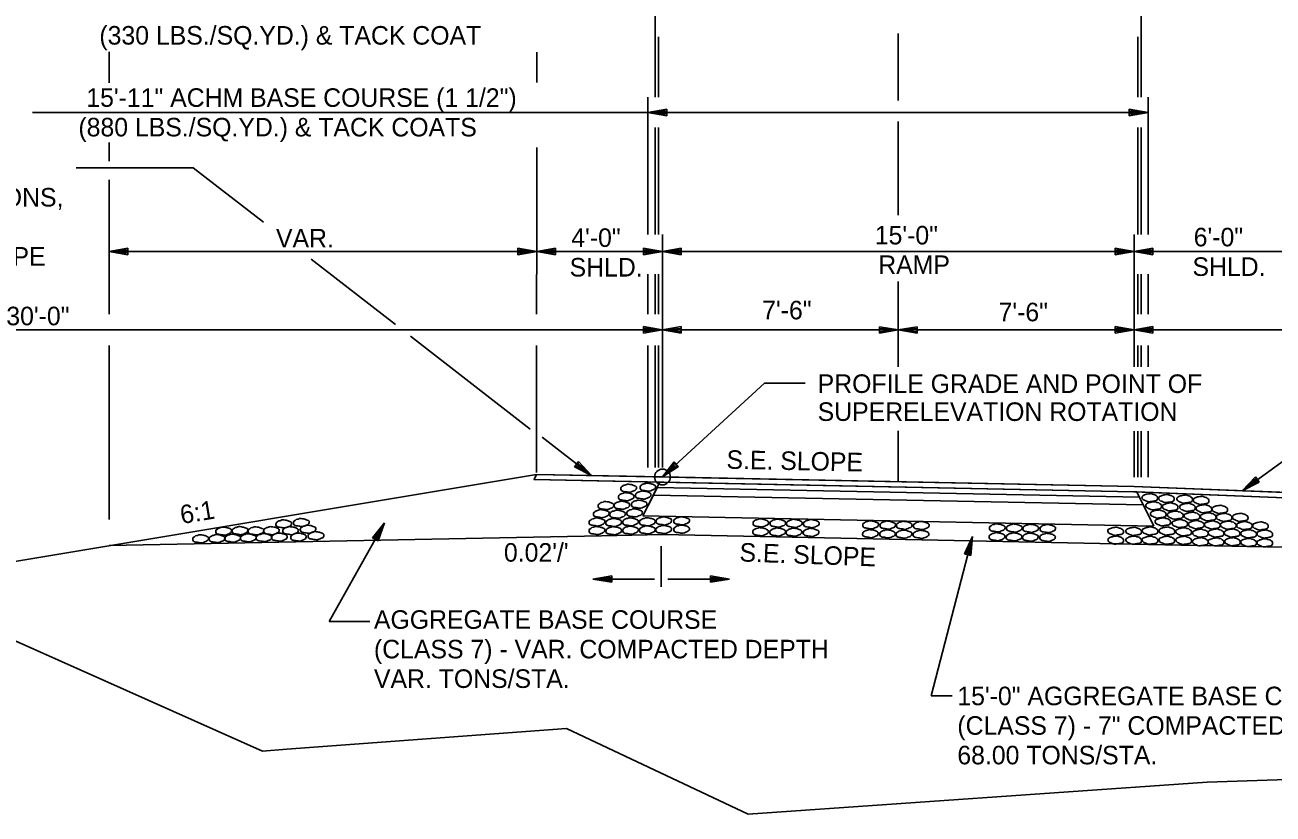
# Model space of a CAD drawing. Extents: x 1734743 to 1735935, y 759845 to 763831.
# Drawn here: x 1735729.77 to 1735769.47, y 762681.39 to 762706.48 of the extents above; entities that cross this region are included whole.
import ezdxf

# ---------------------------------------------------------------- set-up
doc = ezdxf.new("R2010")
doc.units = 0
for name, color, linetype in [('1', 7, 'Continuous'), ('19', 7, 'Continuous'), ('8', 7, 'Continuous'), ('Level 1', 7, 'Continuous'), ('Level 9', 7, 'Continuous'), ('R_Prop Surface', 7, 'Continuous')]:
    doc.layers.add(name, color=color, linetype=linetype)

# ---------------------------------------------------------------- blocks, each defined once
blk = doc.blocks.new('TM')
at = {"layer": '8'}
for p, q in [((-120.309, 21.181), (-119.787, -20.829)), ((0, 0), (-120.309, 21.181)), ((-31.382, 2.945), (-120.176, 10.512)), ((-119.787, -20.829), (0, 0)), ((-119.911, -10.826), (-31.307, -3.057))]:
    blk.add_line(p, q, dxfattribs=at)
blk = doc.blocks.new('ROCKS')
at = {"layer": '1'}
blk.add_spline([(0.013, 0.06), (0.053, 0.053), (0.107, 0.033), (0.133, 0.013), (0.133, -0.007), (0.12, -0.033), (0.107, -0.04), (0.073, -0.053), (0.033, -0.067), (0.013, -0.067), (-0.02, -0.06), (-0.06, -0.053), (-0.087, -0.047), (-0.113, -0.02), (-0.113, -0.007), (-0.107, 0.02), (-0.087, 0.033), (-0.067, 0.047), (-0.033, 0.053), (-0.02, 0.06), (0.013, 0.06)], degree=3, dxfattribs=at)

msp = doc.modelspace()

# ---------------------------------------------------------------- linework, layer by layer
at = {"layer": '19'}
for p, q in [((1735749.814, 762704.185), (1735749.814, 762707.074)), ((1735765.269, 762704.185), (1735765.269, 762707.074)), ((1735749.92, 762704.185), (1735749.92, 762706.104)), ((1735757.548, 762704.077), (1735757.548, 762706.215)), ((1735765.165, 762704.185), (1735765.165, 762706.104)), ((1735732.446, 762704.64), (1735732.446, 762705.631)), ((1735746.047, 762704.651), (1735746.047, 762705.614)), ((1735749.582, 762699.821), (1735749.582, 762704.185)), ((1735765.495, 762699.821), (1735765.495, 762704.185)), ((1735730.014, 762703.7), (1735749.582, 762703.7)), ((1735750.182, 762703.805), (1735749.582, 762703.7)), ((1735749.582, 762699.821), (1735749.582, 762703.7)), ((1735749.582, 762703.7), (1735765.495, 762703.7)), ((1735749.582, 762703.7), (1735750.182, 762703.595)), ((1735750.182, 762703.75), (1735749.742, 762703.715)), ((1735749.742, 762703.685), (1735750.182, 762703.645)), ((1735750.182, 762703.595), (1735750.182, 762703.805)), ((1735764.895, 762703.805), (1735764.895, 762703.595)), ((1735765.495, 762703.7), (1735764.895, 762703.805)), ((1735765.335, 762703.715), (1735764.895, 762703.75)), ((1735764.895, 762703.595), (1735765.495, 762703.7)), ((1735764.895, 762703.645), (1735765.335, 762703.685)), ((1735749.814, 762699.821), (1735749.814, 762703.215)), ((1735749.92, 762699.821), (1735749.92, 762703.215)), ((1735757.547, 762700.429), (1735757.548, 762703.406)), ((1735765.165, 762699.821), (1735765.165, 762703.215)), ((1735765.269, 762699.821), (1735765.269, 762703.215)), ((1735732.446, 762702.153), (1735732.446, 762702.744)), ((1735746.047, 762699.821), (1735746.047, 762702.582)), ((1735731.401, 762701.942), (1735735.119, 762701.942)), ((1735735.119, 762701.942), (1735737.356, 762700.207)), ((1735732.446, 762697.285), (1735732.446, 762701.554)), ((1735746.046, 762697.285), (1735746.047, 762699.821)), ((1735746.046, 762697.285), (1735746.047, 762699.821)), ((1735750.046, 762692.405), (1735750.047, 762699.821)), ((1735750.046, 762692.405), (1735750.047, 762699.821)), ((1735765.046, 762695.613), (1735765.047, 762699.819)), ((1735733.046, 762699.381), (1735732.446, 762699.276)), ((1735732.446, 762699.276), (1735746.046, 762699.275)), ((1735732.446, 762699.276), (1735733.046, 762699.171)), ((1735733.046, 762699.326), (1735732.606, 762699.291)), ((1735732.606, 762699.261), (1735733.046, 762699.221)), ((1735733.046, 762699.171), (1735733.046, 762699.381)), ((1735745.447, 762699.38), (1735745.447, 762699.17)), ((1735746.047, 762699.275), (1735745.447, 762699.38)), ((1735745.887, 762699.29), (1735745.447, 762699.325)), ((1735745.447, 762699.17), (1735746.047, 762699.275)), ((1735745.447, 762699.22), (1735745.887, 762699.26)), ((1735746.647, 762699.381), (1735746.047, 762699.276)), ((1735746.047, 762699.276), (1735750.047, 762699.275)), ((1735746.047, 762699.276), (1735746.647, 762699.171)), ((1735746.647, 762699.326), (1735746.207, 762699.291)), ((1735746.207, 762699.261), (1735746.647, 762699.221)), ((1735746.647, 762699.171), (1735746.647, 762699.381)), ((1735749.447, 762699.381), (1735749.447, 762699.171)), ((1735750.047, 762699.275), (1735749.447, 762699.381)), ((1735749.887, 762699.29), (1735749.447, 762699.326)), ((1735749.447, 762699.171), (1735750.047, 762699.275)), ((1735749.447, 762699.221), (1735749.887, 762699.26)), ((1735750.647, 762699.381), (1735750.047, 762699.276)), ((1735750.047, 762699.276), (1735750.647, 762699.171)), ((1735750.047, 762699.275), (1735765.047, 762699.275)), ((1735750.647, 762699.326), (1735750.207, 762699.291)), ((1735750.207, 762699.261), (1735750.647, 762699.221)), ((1735750.647, 762699.171), (1735750.647, 762699.381)), ((1735764.447, 762699.381), (1735764.447, 762699.171)), ((1735765.047, 762699.275), (1735764.447, 762699.381)), ((1735764.887, 762699.29), (1735764.447, 762699.326)), ((1735764.447, 762699.171), (1735765.047, 762699.275)), ((1735764.447, 762699.221), (1735764.887, 762699.26)), ((1735765.647, 762699.38), (1735765.047, 762699.275)), ((1735765.047, 762699.275), (1735771.047, 762699.275)), ((1735765.047, 762699.275), (1735765.647, 762699.17)), ((1735765.647, 762699.325), (1735765.207, 762699.29)), ((1735765.207, 762699.26), (1735765.647, 762699.22)), ((1735765.647, 762699.17), (1735765.647, 762699.38)), ((1735738.871, 762699.032), (1735741.551, 762696.953)), ((1735749.582, 762697.285), (1735749.582, 762698.553)), ((1735749.813, 762697.285), (1735749.813, 762698.553)), ((1735749.92, 762697.285), (1735749.92, 762698.553)), ((1735757.546, 762695.613), (1735757.547, 762698.325)), ((1735765.165, 762697.284), (1735765.165, 762698.553)), ((1735765.269, 762697.284), (1735765.269, 762698.553)), ((1735765.495, 762697.284), (1735765.495, 762698.553)), ((1735720.041, 762696.787), (1735750.046, 762696.784)), ((1735749.441, 762696.888), (1735749.441, 762696.678)), ((1735750.041, 762696.783), (1735749.441, 762696.888)), ((1735749.881, 762696.798), (1735749.441, 762696.833)), ((1735749.441, 762696.678), (1735750.041, 762696.783)), ((1735749.441, 762696.728), (1735749.881, 762696.768)), ((1735750.046, 762696.785), (1735757.546, 762696.785)), ((1735750.647, 762696.886), (1735750.047, 762696.781)), ((1735750.047, 762696.781), (1735750.647, 762696.676)), ((1735750.647, 762696.831), (1735750.207, 762696.796)), ((1735750.207, 762696.766), (1735750.647, 762696.726)), ((1735750.647, 762696.676), (1735750.647, 762696.886)), ((1735756.947, 762696.885), (1735756.947, 762696.675)), ((1735757.547, 762696.78), (1735756.947, 762696.885)), ((1735757.387, 762696.795), (1735756.947, 762696.83)), ((1735756.947, 762696.675), (1735757.547, 762696.78)), ((1735756.947, 762696.725), (1735757.387, 762696.765)), ((1735757.546, 762696.785), (1735765.046, 762696.784)), ((1735758.147, 762696.885), (1735757.547, 762696.78)), ((1735757.547, 762696.78), (1735758.147, 762696.675)), ((1735758.147, 762696.83), (1735757.707, 762696.795)), ((1735757.707, 762696.765), (1735758.147, 762696.725)), ((1735758.147, 762696.675), (1735758.147, 762696.885)), ((1735764.446, 762696.889), (1735764.446, 762696.679)), ((1735765.046, 762696.784), (1735764.446, 762696.889)), ((1735764.886, 762696.799), (1735764.446, 762696.834)), ((1735764.446, 762696.679), (1735765.046, 762696.784)), ((1735764.446, 762696.729), (1735764.886, 762696.769)), ((1735765.646, 762696.889), (1735765.046, 762696.784)), ((1735765.046, 762696.784), (1735765.646, 762696.679)), ((1735765.046, 762696.784), (1735795.041, 762696.782)), ((1735765.646, 762696.834), (1735765.206, 762696.799)), ((1735765.206, 762696.769), (1735765.646, 762696.729)), ((1735765.646, 762696.679), (1735765.646, 762696.889)), ((1735742.03, 762696.581), (1735745.838, 762693.627)), ((1735732.446, 762690.751), (1735732.446, 762696.285)), ((1735746.046, 762692.246), (1735746.046, 762696.285)), ((1735746.046, 762692.246), (1735746.046, 762696.285)), ((1735749.581, 762692.405), (1735749.581, 762696.285)), ((1735749.813, 762692.405), (1735749.813, 762696.285)), ((1735749.919, 762692.405), (1735749.919, 762696.285)), ((1735765.165, 762695.613), (1735765.165, 762696.284)), ((1735765.269, 762695.613), (1735765.269, 762696.284)), ((1735765.495, 762695.613), (1735765.495, 762696.284)), ((1735753.294, 762695.086), (1735750.046, 762692.105)), ((1735754.584, 762695.086), (1735753.294, 762695.086)), ((1735757.546, 762691.955), (1735757.547, 762693.568)), ((1735765.046, 762692.104), (1735765.046, 762693.567)), ((1735765.165, 762692.104), (1735765.165, 762693.567)), ((1735765.269, 762692.104), (1735765.269, 762693.567)), ((1735765.495, 762692.104), (1735765.495, 762693.567)), ((1735746.216, 762693.37), (1735747.788, 762692.151)), ((1735768.483, 762691.667), (1735770.684, 762693.264)), ((1735747.245, 762692.428), (1735747.372, 762692.595)), ((1735747.788, 762692.151), (1735747.245, 762692.428)), ((1735747.655, 762692.238), (1735747.282, 762692.468)), ((1735747.346, 762692.556), (1735747.668, 762692.26)), ((1735747.372, 762692.595), (1735747.788, 762692.151)), ((1735750.046, 762692.105), (1735750.418, 762692.588)), ((1735750.558, 762692.434), (1735750.046, 762692.105)), ((1735750.156, 762692.22), (1735750.45, 762692.545)), ((1735750.525, 762692.465), (1735750.175, 762692.203)), ((1735750.418, 762692.588), (1735750.558, 762692.434)), ((1735746.046, 762692.186), (1735720.048, 762687.858)), ((1735745.963, 762692.021), (1735765.043, 762691.638)), ((1735746.046, 762692.186), (1735765.046, 762691.804)), ((1735768.483, 762691.667), (1735768.905, 762692.105)), ((1735768.604, 762691.769), (1735768.933, 762692.059)), ((1735768.998, 762691.972), (1735768.621, 762691.75)), ((1735768.905, 762692.105), (1735769.028, 762691.937)), ((1735749.881, 762691.775), (1735749.757, 762691.528)), ((1735749.881, 762691.775), (1735765.214, 762691.467)), ((1735765.214, 762691.467), (1735749.881, 762691.775)), ((1735765.039, 762691.638), (1735771.131, 762691.394)), ((1735765.046, 762691.804), (1735771.046, 762691.564)), ((1735769.028, 762691.937), (1735768.483, 762691.667)), ((1735749.757, 762691.528), (1735749.427, 762690.868)), ((1735749.757, 762691.528), (1735765.341, 762691.215)), ((1735749.757, 762691.528), (1735765.341, 762691.215)), ((1735765.341, 762691.215), (1735749.757, 762691.528)), ((1735765.341, 762691.215), (1735765.214, 762691.467)), ((1735765.677, 762690.541), (1735765.341, 762691.215)), ((1735749.427, 762690.868), (1735765.677, 762690.541)), ((1735749.427, 762690.868), (1735765.677, 762690.541)), ((1735739.449, 762687.514), (1735741.205, 762690.647)), ((1735740.821, 762690.175), (1735741.205, 762690.647)), ((1735740.862, 762690.155), (1735741.113, 762690.514)), ((1735741.136, 762690.503), (1735740.958, 762690.103)), ((1735741.205, 762690.647), (1735741.002, 762690.072)), ((1735748.108, 762690.233), (1735732.446, 762689.922)), ((1735741.002, 762690.072), (1735740.821, 762690.175)), ((1735750.046, 762690.272), (1735748.108, 762690.233)), ((1735750.046, 762690.272), (1735767.056, 762689.93)), ((1735758.588, 762685.141), (1735759.905, 762690.214)), ((1735759.653, 762689.66), (1735759.905, 762690.214)), ((1735759.699, 762689.651), (1735759.85, 762690.062)), ((1735759.875, 762690.058), (1735759.805, 762689.625)), ((1735759.905, 762690.214), (1735759.855, 762689.607)), ((1735750.006, 762689.903), (1735750.006, 762688.615)), ((1735759.855, 762689.607), (1735759.653, 762689.66)), ((1735767.055, 762689.93), (1735782.73, 762689.615)), ((1735749.789, 762688.853), (1735747.835, 762688.853)), ((1735750.222, 762688.853), (1735752.177, 762688.853)), ((1735740.739, 762687.514), (1735739.449, 762687.514)), ((1735759.264, 762685.141), (1735758.588, 762685.141))]:
    msp.add_line(p, q, dxfattribs=at)
for points in [[(1735680.306, 762694.946), (1735680.306, 762694.946), (1735680.306, 762694.946), (1735688.042, 762694.993), (1735690.336, 762695.104), (1735696.399, 762695.063), (1735703.199, 762694.723), (1735715.078, 762692.342), (1735728.668, 762687.241), (1735737.329, 762683.386), (1735738.102, 762683.447)], [(1735771.131, 762691.394), (1735765.131, 762691.634), (1735765.041, 762691.638), (1735749.964, 762691.94), (1735749.964, 762691.94), (1735749.964, 762691.94), (1735745.963, 762692.021), (1735746.046, 762692.186), (1735746.046, 762692.186), (1735750.046, 762692.105), (1735765.046, 762691.804), (1735771.046, 762691.564), (1735771.046, 762691.564), (1735771.131, 762691.394), (1735771.131, 762691.394), (1735771.131, 762691.394)], [(1735765.214, 762691.467), (1735749.881, 762691.775), (1735749.881, 762691.775), (1735749.964, 762691.94), (1735749.964, 762691.94), (1735765.041, 762691.638), (1735765.131, 762691.634), (1735765.131, 762691.634), (1735765.131, 762691.634), (1735765.131, 762691.634), (1735765.214, 762691.467), (1735765.214, 762691.467), (1735765.214, 762691.467)], [(1735738.102, 762683.447), (1735746.995, 762684.106), (1735752.775, 762681.385), (1735767.375, 762682.404), (1735787.755, 762683.082), (1735799.985, 762684.441), (1735809.495, 762682.741), (1735820.81, 762685.178), (1735822.413, 762684.867)]]:
    msp.add_lwpolyline(points, dxfattribs=at)
at = {"layer": 'Level 9'}
msp.add_circle((1735750.046, 762692.105), 0.25, dxfattribs=at)
at = {"layer": 'R_Prop Surface'}
for p, q in [((1735746.046, 762692.186), (1735745.963, 762692.021)), ((1735749.964, 762691.94), (1735749.427, 762690.868)), ((1735765.131, 762691.634), (1735765.677, 762690.541))]:
    msp.add_line(p, q, dxfattribs=at)

# ---------------------------------------------------------------- block references
at = {"layer": '19', "xscale": 0.0050063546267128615}
for p, yscale, rotation in [((1735747.833, 762688.851), -0.00500635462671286, -179.20057588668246), ((1735752.178, 762688.851), 0.00500635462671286, -0.7994241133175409)]:
    msp.add_blockref('TM', p, dxfattribs=dict(at, yscale=yscale, rotation=rotation))
at = {"layer": 'Level 1'}
for p, xscale, yscale, rotation in [((1735748.873, 762691.483), 2.011654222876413, 2.0116542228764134, 2.041282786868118), ((1735748.95, 762691.751), 2.011654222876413, 2.0116542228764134, 2.041282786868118), ((1735749.414, 762691.537), 2.011654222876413, 2.0116542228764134, 2.041282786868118), ((1735749.561, 762691.786), 2.011654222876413, 2.0116542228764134, 2.041282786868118), ((1735765.567, 762691.452), 2.0116542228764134, -2.011654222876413, 177.9586193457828), ((1735748.228, 762691.201), 2.011654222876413, 2.0116542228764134, 2.041282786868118), ((1735748.734, 762691.21), 2.011654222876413, 2.0116542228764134, 2.041282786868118), ((1735749.285, 762691.245), 2.011654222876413, 2.0116542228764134, 2.041282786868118), ((1735765.691, 762691.193), 2.0116542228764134, -2.011654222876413, 177.9586193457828), ((1735766.099, 762691.423), 2.0116542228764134, -2.011654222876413, 177.9586193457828), ((1735766.217, 762691.158), 2.0116542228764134, -2.011654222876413, 177.9586193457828), ((1735766.679, 762691.407), 2.011654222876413, -2.0116542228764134, 177.95871721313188), ((1735766.766, 762691.145), 2.011654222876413, -2.0116542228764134, 177.95871721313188), ((1735767.198, 762691.367), 2.011654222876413, -2.0116542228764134, 177.95871721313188), ((1735767.289, 762691.1), 2.011654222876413, -2.0116542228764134, 177.95871721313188), ((1735767.793, 762691.08), 2.011654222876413, -2.0116542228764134, 177.95871721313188), ((1735738.539, 762690.662), 2.011654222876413, 2.011654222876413, 1.8263814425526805), ((1735747.943, 762690.679), 2.011654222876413, 2.0116542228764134, 2.041282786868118), ((1735748.082, 762690.944), 2.011654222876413, 2.0116542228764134, 2.041282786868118), ((1735748.476, 762690.663), 2.011654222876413, 2.0116542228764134, 2.041282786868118), ((1735748.597, 762690.926), 2.011654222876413, 2.0116542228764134, 2.041282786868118), ((1735749.01, 762690.683), 2.011654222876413, 2.0116542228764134, 2.041282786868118), ((1735749.138, 762690.968), 2.011654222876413, 2.0116542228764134, 2.041282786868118), ((1735749.545, 762690.685), 2.011654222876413, 2.0116542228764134, 2.041282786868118), ((1735750.069, 762690.711), 2.011654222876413, 2.0116542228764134, 2.041282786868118), ((1735750.639, 762690.715), 2.011654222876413, 2.0116542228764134, 2.041282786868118), ((1735753.154, 762690.649), 2.011654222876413, 2.011654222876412, 1.0597939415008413), ((1735753.697, 762690.641), 2.011654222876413, 2.011654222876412, 1.0597939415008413), ((1735765.836, 762690.932), 2.0116542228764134, -2.011654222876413, 177.9586193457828), ((1735765.983, 762690.683), 2.0116542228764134, -2.011654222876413, 177.9586193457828), ((1735766.381, 762690.897), 2.0116542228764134, -2.011654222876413, 177.9586193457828), ((1735766.91, 762690.863), 2.0116542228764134, -2.011654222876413, 177.9586193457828), ((1735767.427, 762690.843), 2.011654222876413, -2.0116542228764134, 177.95871721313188), ((1735767.932, 762690.827), 2.011654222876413, -2.0116542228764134, 177.95871721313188), ((1735768.444, 762690.825), 2.011654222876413, -2.0116542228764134, 177.95871721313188), ((1735736.07, 762690.389), 2.011654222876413, 2.011654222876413, 1.8263814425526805), ((1735736.591, 762690.404), 2.011654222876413, 2.011654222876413, 1.8263814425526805), ((1735737.097, 762690.397), 2.011654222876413, 2.011654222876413, 1.8263814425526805), ((1735737.59, 762690.403), 2.011654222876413, 2.011654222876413, 1.8263814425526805), ((1735737.981, 762690.618), 2.011654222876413, 2.011654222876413, 1.8263814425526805), ((1735738.198, 762690.403), 2.011654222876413, 2.011654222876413, 1.8263814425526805), ((1735738.756, 762690.447), 2.011654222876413, 2.011654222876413, 1.8263814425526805), ((1735739.008, 762690.242), 2.011654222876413, 2.011654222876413, 1.8263814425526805), ((1735747.944, 762690.408), 2.011654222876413, 2.0116542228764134, 2.041282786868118), ((1735748.477, 762690.402), 2.011654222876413, 2.0116542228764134, 2.041282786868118), ((1735749.011, 762690.418), 2.011654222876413, 2.0116542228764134, 2.041282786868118), ((1735749.546, 762690.429), 2.011654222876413, 2.0116542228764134, 2.041282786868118), ((1735750.065, 762690.441), 2.011654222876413, 2.0116542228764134, 2.041282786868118), ((1735750.635, 762690.451), 2.011654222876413, 2.0116542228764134, 2.041282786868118), ((1735753.145, 762690.369), 2.011654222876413, 2.011654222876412, 1.0597939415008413), ((1735753.688, 762690.361), 2.011654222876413, 2.011654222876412, 1.0597939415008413), ((1735754.21, 762690.354), 2.011654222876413, 2.011654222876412, 1.0597939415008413), ((1735754.219, 762690.634), 2.011654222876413, 2.011654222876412, 1.0597939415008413), ((1735754.753, 762690.347), 2.011654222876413, 2.011654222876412, 1.0597939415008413), ((1735754.762, 762690.627), 2.011654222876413, 2.011654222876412, 1.0597939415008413), ((1735756.641, 762690.308), 2.011654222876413, 2.0116542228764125, 1.0296627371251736), ((1735756.65, 762690.588), 2.011654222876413, 2.0116542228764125, 1.0296627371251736), ((1735757.184, 762690.3), 2.011654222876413, 2.0116542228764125, 1.0296627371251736), ((1735757.193, 762690.58), 2.011654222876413, 2.0116542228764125, 1.0296627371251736), ((1735757.706, 762690.293), 2.011654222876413, 2.0116542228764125, 1.0296627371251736), ((1735757.715, 762690.573), 2.011654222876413, 2.0116542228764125, 1.0296627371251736), ((1735758.249, 762690.286), 2.011654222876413, 2.0116542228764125, 1.0296627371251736), ((1735758.258, 762690.565), 2.011654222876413, 2.0116542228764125, 1.0296627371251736), ((1735760.675, 762690.492), 2.011654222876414, 2.011654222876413, 1.0074964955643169), ((1735761.218, 762690.485), 2.011654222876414, 2.011654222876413, 1.0074964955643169), ((1735761.74, 762690.477), 2.011654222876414, 2.011654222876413, 1.0074964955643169), ((1735762.282, 762690.469), 2.011654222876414, 2.011654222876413, 1.0074964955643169), ((1735764.482, 762690.383), 2.0116542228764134, -2.011654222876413, 177.9586193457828), ((1735765.053, 762690.381), 2.0116542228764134, -2.011654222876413, 177.9586193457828), ((1735765.576, 762690.393), 2.0116542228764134, -2.011654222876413, 177.9586193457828), ((1735766.112, 762690.391), 2.0116542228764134, -2.011654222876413, 177.9586193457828), ((1735766.524, 762690.628), 2.0116542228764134, -2.011654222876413, 177.9586193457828), ((1735766.646, 762690.366), 2.0116542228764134, -2.011654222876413, 177.9586193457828), ((1735767.046, 762690.595), 2.0116542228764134, -2.011654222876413, 177.9586193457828), ((1735767.179, 762690.32), 2.0116542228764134, -2.011654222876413, 177.9586193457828), ((1735767.557, 762690.584), 2.011654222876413, -2.0116542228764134, 177.95871721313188), ((1735767.674, 762690.328), 2.011654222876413, -2.0116542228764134, 177.95871721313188), ((1735768.067, 762690.579), 2.011654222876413, -2.0116542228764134, 177.95871721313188), ((1735768.185, 762690.327), 2.011654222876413, -2.0116542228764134, 177.95871721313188), ((1735768.58, 762690.564), 2.011654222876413, -2.0116542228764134, 177.95871721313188), ((1735768.712, 762690.303), 2.011654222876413, -2.0116542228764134, 177.95871721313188), ((1735769.088, 762690.552), 2.011654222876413, -2.0116542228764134, 177.95871721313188), ((1735769.226, 762690.297), 2.011654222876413, -2.0116542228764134, 177.95871721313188), ((1735735.338, 762690.144), 2.011654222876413, 2.011654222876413, 1.8263814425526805), ((1735735.859, 762690.15), 2.011654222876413, 2.011654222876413, 1.8263814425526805), ((1735736.359, 762690.164), 2.011654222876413, 2.011654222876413, 1.8263814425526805), ((1735736.855, 762690.175), 2.011654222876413, 2.011654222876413, 1.8263814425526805), ((1735737.351, 762690.182), 2.011654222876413, 2.011654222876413, 1.8263814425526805), ((1735737.842, 762690.198), 2.011654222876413, 2.011654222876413, 1.8263814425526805), ((1735738.45, 762690.198), 2.011654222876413, 2.011654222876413, 1.8263814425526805), ((1735760.665, 762690.212), 2.011654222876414, 2.011654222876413, 1.0074964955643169), ((1735761.209, 762690.205), 2.011654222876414, 2.011654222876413, 1.0074964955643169), ((1735761.73, 762690.197), 2.011654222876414, 2.011654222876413, 1.0074964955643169), ((1735762.273, 762690.189), 2.011654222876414, 2.011654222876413, 1.0074964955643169), ((1735764.487, 762690.103), 2.0116542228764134, -2.011654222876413, 177.9586193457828), ((1735765.057, 762690.101), 2.0116542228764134, -2.011654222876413, 177.9586193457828), ((1735765.575, 762690.099), 2.0116542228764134, -2.011654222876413, 177.9586193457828), ((1735766.111, 762690.097), 2.0116542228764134, -2.011654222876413, 177.9586193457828), ((1735766.645, 762690.095), 2.0116542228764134, -2.011654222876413, 177.9586193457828), ((1735767.178, 762690.05), 2.0116542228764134, -2.011654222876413, 177.9586193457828), ((1735767.674, 762690.047), 2.011654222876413, -2.0116542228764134, 177.95871721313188), ((1735768.199, 762690.051), 2.011654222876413, -2.0116542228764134, 177.95871721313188), ((1735768.712, 762690.027), 2.011654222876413, -2.0116542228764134, 177.95871721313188), ((1735769.226, 762690.016), 2.011654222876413, -2.0116542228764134, 177.95871721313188)]:
    msp.add_blockref('ROCKS', p, dxfattribs=dict(at, xscale=xscale, yscale=yscale, rotation=rotation))

# ---------------------------------------------------------------- texts
at = {"layer": '19'}
for s, height, rotation, p in [('(330 LBS./SQ.YD.) & TACK COAT', 0.59001, 359.9954, (1735732.138, 762705.857)), ('15\'-11" ACHM BASE COURSE (1 1/2")', 0.59001, 359.9954, (1735731.722, 762703.877)), ('(880 LBS./SQ.YD.) & TACK COATS', 0.59001, 359.9954, (1735731.471, 762702.937)), ('THROUGH SUPERELEVATION TRANSITIONS,', 0.59001, 360, (1735713.898, 762700.707)), ('VAR.', 0.59, 359.9954, (1735737.755, 762699.405)), ('4\'-0"', 0.59, 359.9954, (1735747.147, 762699.422)), ('15\'-0"', 0.59, 359.9954, (1735756.8, 762699.501)), ('6\'-0"', 0.59, 359.9954, (1735766.943, 762699.44)), ('PAVEMENT SLOPE AND SHOULDER SLOPE', 0.59001, 360, (1735713.898, 762698.827)), ('RAMP', 0.59, 359.9954, (1735756.911, 762698.561)), ('SHLD.', 0.59, 359.9954, (1735747.094, 762698.481)), ('SHLD.', 0.59, 359.9954, (1735766.904, 762698.5)), ('30\'-0"', 0.59, 0.0046, (1735729.178, 762696.93)), ('7\'-6"', 0.59, 359.9954, (1735753.219, 762697.119)), ('7\'-6"', 0.59, 359.9954, (1735760.737, 762697.057)), ('PROFILE GRADE AND POINT OF ', 0.59001, 359.9954, (1735754.983, 762694.778)), ('SUPERELEVATION ROTATION', 0.59001, 359.9954, (1735754.983, 762693.888)), ('S.E. SLOPE', 0.59, 358.8496, (1735752.079, 762692.368)), ('6:1', 0.59, 9.4465, (1735734.757, 762690.607)), ("0.02'/'", 0.59, 359.9954, (1735745.005, 762689.412)), ('S.E. SLOPE', 0.59, 357.8898, (1735752.489, 762689.42)), ('AGGREGATE BASE COURSE', 0.59001, 360, (1735740.871, 762687.276)), ('(CLASS 7) - VAR. COMPACTED DEPTH', 0.59001, 360, (1735740.871, 762686.336)), ('VAR. TONS/STA.', 0.59001, 360, (1735740.871, 762685.396)), ('15\'-0" AGGREGATE BASE COURSE', 0.59001, 360, (1735759.426, 762684.846)), ('(CLASS 7) - 7" COMPACTED DEPTH', 0.59001, 360, (1735759.426, 762683.906)), ('68.00 TONS/STA.', 0.59001, 360, (1735759.426, 762682.966))]:
    msp.add_text(s, height=height, rotation=rotation, dxfattribs=at).set_placement(p)

doc.saveas('drawing.dxf')
